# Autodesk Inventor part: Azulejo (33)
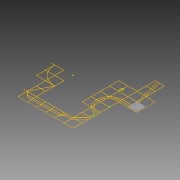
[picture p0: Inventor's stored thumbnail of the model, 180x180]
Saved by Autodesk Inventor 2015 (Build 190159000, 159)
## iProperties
Created: 2015-04
Part Number: Azulejo (33)
Material: Genérico
Document SubType Name: Modeling
Designer: Felipe
Density: 1 g/cm^3
Appearance: Padrão
Author: Felipe
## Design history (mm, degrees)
sketch "Sketch1"
  geometry: L1 (-1510, -7490)-(-1510, -6010); L2 (-3010, -1490)-(-3010, -10); L3 (-2990, 10)-(-1510, 10); L4 (-1510, -10)-(-2990, -10); L5 (-1510, -1490)-(-1510, -10); L6 (-1490, -10)-(-1490, -1490); L7 (-1490, -1490)-(-10, -1490); L8 (-10, -1510)-(-1490, -1510); L9 (-10, -2990)-(-10, -1510); L10 (-10, -5990)-(-10, -4510); L11 (-1490, -7490)-(-10, -7490); L12 (4490, -6010)-(3010, -6010); L13 (10, -1510)-(10, -2990); L14 (10, -3010)-(10, -4490); L15 (10, -4510)-(10, -5990); L16 (10, -5990)-(1490, -5990); L17 (1490, -6010)-(10, -6010); L18 (10, -7490)-(1490, -7490); L19 (1510, -5990)-(2990, -5990); L20 (2990, -6010)-(1510, -6010); L21 (1510, -7490)-(2990, -7490); L22 (4490, 1510)-(4490, 2990); L23 (4490, 10)-(4490, 1490); L24 (4490, -1490)-(4490, -10); L25 (4490, -2990)-(4490, -1510); L26 (3010, -5990)-(4490, -5990); L27 (3010, -7490)-(4490, -7490); L28 (4510, 3010)-(5990, 3010); L29 (5990, 2990)-(4510, 2990); L30 (4510, 2990)-(4510, 1510); L31 (4510, 1510)-(5990, 1510); L32 (5990, 1510)-(5990, 1740.185); L33 (5990, 1760.2)-(5990, 2259.8); L34 (5990, 2279.815)-(5990, 2990); L35 (5990, 1490)-(4510, 1490); L36 (4510, 1490)-(4510, 10); L37 (4510, 10)-(5990, 10); L38 (5990, 10)-(5990, 1490); L39 (5975.983, -10)-(4510, -10); L40 (4510, -10)-(4510, -1490); L41 (5990, -1510)-(5782.897, -1510); L42 (5782.897, -1510)-(5688.66, -1510); L43 (5668.66, -1510)-(5482.895, -1510); L44 (5482.895, -1510)-(5388.656, -1510); L45 (5368.656, -1510)-(4510, -1510); L46 (4510, -1510)-(4510, -2990); L47 (4510, -2990)-(5975.983, -2990); L48 (5990, -2975.728)-(5990, -2837.377); L49 (5990, -2837.377)-(5990, -2536.247); L50 (5990, -2500.476)-(5990, -2317.632); L51 (5990, -2317.632)-(5990, -1510); L52 (5990, -3010)-(4510, -3010); L53 (5990, -4490)-(5990, -3010); L54 (4510, -5990)-(5990, -5990); L55 (5990, -5990)-(5990, -4510); L56 (4510, -7490)-(5990, -7490); L57 (5990, -7490)-(5990, -6310); L58 (5990, -6290)-(5990, -6010); L59 (7490, 4510)-(7490, 5990); L60 (6010, 3010)-(7490, 3010); L61 (7490, 3010)-(7490, 4490); L62 (7490, 2990)-(6010, 2990); L63 (6010, 2990)-(6010, 2279.815); L64 (6010, 2259.8)-(6010, 1760.2)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; A1 r 250 centre (6000, 2010) between (5990, 2259.8) and (5990, 1760.2); A2 r 250 centre (6000, 2010) between (6010, 1760.2) and (6010, 2259.8); A3 r 270 centre (6000, 2010) between (5990, 2279.815) and (5990, 1740.185); A4 r 270 centre (6000, 2010) between (6010, 1740.185) and (6010, 2279.815); A5 r 3010.017 centre (0, 0) between (-1490, -2615.358) and (-346.554, -2990); A6 r 2990.017 centre (0, 0) between (-1490, -2592.316) and (-10, -2990); A7 r 3010.017 centre (0, 0) between (-2603.863, -1510) and (-1510, -2603.863); A8 r 2990.017 centre (0, 0) between (-2580.717, -1510) and (-1510, -2580.717); A9 r 3010.017 centre (0, 0) between (-2990, -346.554) and (-2615.358, -1490); A10 r 2990.017 centre (0, 0) between (-2990, -10) and (-2592.316, -1490); A11 r 2131.367 centre (7500, -1500) between (7490, 631.344) and (6010, 24.017); A12 r 2131.367 centre (7500, -1500) between (5975.983, -10) and (5368.656, -1490); A13 r 2131.367 centre (7500, -1500) between (5368.656, -1510) and (5975.983, -2990); A14 r 2131.367 centre (7500, -1500) between (6010, -3024.017) and (7190, -3608.703); A15 r 1831.367 centre (7500, -1500) between (7490.321, 331.342) and (6463.753, 10); A16 r 1831.367 centre (7500, -1500) between (6435.196, -10) and (6010, -435.196); A17 r 1831.367 centre (7500, -1500) between (5990, -463.753) and (5668.66, -1490); A18 r 1831.367 centre (7500, -1500) between (5668.66, -1510) and (5990, -2536.247); A19 r 1831.367 centre (7500, -1500) between (6010, -2564.804) and (6435.196, -2990); A20 r 1831.367 centre (7500, -1500) between (6463.753, -3010) and (7490, -3331.34); A21 r 2111.367 centre (7500, -1500) between (7490.047, 611.344) and (6024.272, 10); A22 r 2111.367 centre (7500, -1500) between (5990, -24.272) and (5388.656, -1490); A23 r 2111.367 centre (7500, -1500) between (5388.656, -1510) and (5990, -2975.728); A24 r 2111.367 centre (7500, -1500) between (6024.272, -3010) and (7210, -3591.357); A25 r 1811.367 centre (7500, -1500) between (7490.374, 311.342) and (6499.524, 10); A26 r 1811.367 centre (7500, -1500) between (6469.975, -10) and (6010, -469.975); A27 r 1811.367 centre (7500, -1500) between (5990, -499.524) and (5688.66, -1490); A28 r 1811.367 centre (7500, -1500) between (5688.66, -1510) and (5990, -2500.476); A29 r 1811.367 centre (7500, -1500) between (6010, -2530.025) and (6469.975, -2990); A30 r 1811.367 centre (7500, -1500) between (6499.524, -3010) and (7490, -3311.34); A31 r 449.871 centre (7499.449, -4060.672) between (7510, -4510.419) and (7521.546, -4510); 9 further points
  constraints: 698 end point, 64 point on circle, 31 centre point, 11 point on line, 1 other
extrude "Extrusion1" new body sketch "Sketch1" distance "d0" = 60; taper "d1" = 0 deg
extrude "Extrusion2" new body sketch "Sketch1" distance "d2" = 60; taper "d3" = 0 deg
body "Solid1"
body "Solid2"
